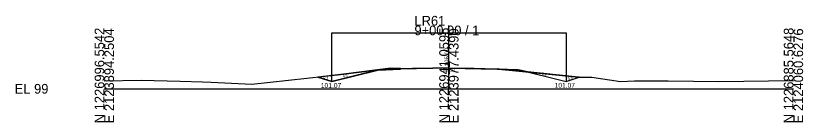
# Model space of a CAD drawing. Extents: x 2121193 to 2127979, y 1225108 to 1234639.
# Drawn here: x 2126750.9 to 2126979.4, y 1234107.5 to 1234138.4 of the extents above; entities that cross this region are included whole.
import ezdxf

# ---------------------------------------------------------------- set-up
doc = ezdxf.new("R2010")
doc.units = 0
for name, color, linetype in [('XS_CELL', 7, 'Continuous'), ('XS_M_DITCH', 7, 'Continuous'), ('XS_M_SHAPES_EARTHWORK', 7, 'Continuous'), ('XS_P_FINISHED_GRADE', 7, 'Continuous'), ('XS_P_FINISHED_GRADE_ELEV_TX', 7, 'Continuous'), ('XS_P_SUBGRADE_GRANULAR', 7, 'Continuous'), ('XS_P_SUBGRADE_PAVEMENT', 7, 'Continuous'), ('XS_P_TX_DCH', 7, 'Continuous'), ('XS_P_TX_FS_BS', 7, 'Continuous'), ('XS_X_GROUND', 7, 'Continuous'), ('XS_X_GROUND_TX', 7, 'Continuous')]:
    doc.layers.add(name, color=color, linetype=linetype)

msp = doc.modelspace()

# ---------------------------------------------------------------- linework, layer by layer
at = {"layer": 'XS_CELL'}
for p, q in [((2126876.61, 1234117.21), (2126876.61, 1234135.52)), ((2126776.61, 1234117.21), (2126876.61, 1234117.21)), ((2126876.61, 1234117.21), (2126976.61, 1234117.21))]:
    msp.add_line(p, q, dxfattribs=at)
at = {"layer": 'XS_M_DITCH'}
for p, q in [((2126842.61, 1234119.28), (2126842.61, 1234133.39)), ((2126842.61, 1234133.39), (2126910.61, 1234133.39)), ((2126910.61, 1234133.39), (2126910.61, 1234119.28))]:
    msp.add_line(p, q, dxfattribs=at)
at = {"layer": 'XS_M_SHAPES_EARTHWORK'}
for p, q in [((2126859.71, 1234123.21), (2126846.06, 1234121.41)), ((2126856.02, 1234122.63), (2126862.54, 1234122.89)), ((2126856.61, 1234122.78), (2126856.02, 1234122.63)), ((2126856.61, 1234122.78), (2126862.61, 1234123.02)), ((2126862.61, 1234123.02), (2126856.61, 1234122.78)), ((2126861.73, 1234123.11), (2126859.71, 1234123.21)), ((2126862.61, 1234123.12), (2126861.73, 1234123.11)), ((2126862.54, 1234122.89), (2126862.61, 1234123.02)), ((2126862.61, 1234123.02), (2126862.61, 1234123.12)), ((2126891.99, 1234122.84), (2126890.63, 1234122.98)), ((2126890.63, 1234122.98), (2126890.68, 1234122.89)), ((2126890.68, 1234122.89), (2126891.99, 1234122.84)), ((2126897.2, 1234122.63), (2126891.99, 1234122.84)), ((2126891.99, 1234122.84), (2126899.44, 1234122.07)), ((2126899.44, 1234122.07), (2126897.2, 1234122.63)), ((2126914.27, 1234120.54), (2126899.44, 1234122.07)), ((2126899.44, 1234122.07), (2126910.61, 1234119.28)), ((2126846.06, 1234121.41), (2126838.62, 1234120.61)), ((2126838.62, 1234120.61), (2126842.61, 1234119.28)), ((2126910.61, 1234119.28), (2126914.39, 1234120.54)), ((2126914.39, 1234120.54), (2126914.27, 1234120.54))]:
    msp.add_line(p, q, dxfattribs=at)
msp.add_lwpolyline([(2126842.61, 1234119.28), (2126856.02, 1234122.63), (2126856.61, 1234122.78)], dxfattribs=at)
at = {"layer": 'XS_P_FINISHED_GRADE'}
for p, q in [((2126856.61, 1234122.78), (2126842.61, 1234119.28)), ((2126862.61, 1234123.02), (2126856.61, 1234122.78)), ((2126876.61, 1234123.3), (2126862.61, 1234123.02)), ((2126876.61, 1234123.3), (2126890.61, 1234123.02)), ((2126890.61, 1234123.02), (2126896.61, 1234122.78)), ((2126896.61, 1234122.78), (2126910.61, 1234119.28)), ((2126842.61, 1234119.28), (2126838.62, 1234120.61)), ((2126910.61, 1234119.28), (2126914.39, 1234120.54))]:
    msp.add_line(p, q, dxfattribs=at)
at = {"layer": 'XS_P_SUBGRADE_GRANULAR'}
for p, q in [((2126862.54, 1234122.89), (2126856.02, 1234122.63)), ((2126890.68, 1234122.89), (2126897.2, 1234122.63))]:
    msp.add_line(p, q, dxfattribs=at)
at = {"layer": 'XS_P_SUBGRADE_PAVEMENT'}
for p, q in [((2126876.61, 1234123.17), (2126862.54, 1234122.89)), ((2126862.61, 1234123.02), (2126862.54, 1234122.89)), ((2126876.61, 1234123.17), (2126890.68, 1234122.89)), ((2126890.61, 1234123.02), (2126890.68, 1234122.89))]:
    msp.add_line(p, q, dxfattribs=at)
at = {"layer": 'XS_X_GROUND'}
for p, q in [((2126846.06, 1234121.41), (2126859.71, 1234123.21)), ((2126859.71, 1234123.21), (2126861.73, 1234123.11)), ((2126861.73, 1234123.11), (2126866.03, 1234123.17)), ((2126866.03, 1234123.17), (2126876.05, 1234123.31)), ((2126876.05, 1234123.31), (2126876.61, 1234123.3)), ((2126876.61, 1234123.3), (2126883.92, 1234123.15)), ((2126883.92, 1234123.15), (2126890.34, 1234123.01)), ((2126890.34, 1234123.01), (2126914.27, 1234120.54)), ((2126776.61, 1234119.54), (2126787.36, 1234119.66)), ((2126787.36, 1234119.66), (2126798.62, 1234119.46)), ((2126819.38, 1234118.55), (2126846.06, 1234121.41)), ((2126914.27, 1234120.54), (2126918.1, 1234120.53)), ((2126918.1, 1234120.53), (2126926.43, 1234119.27)), ((2126926.43, 1234119.27), (2126930.49, 1234119.48)), ((2126930.49, 1234119.48), (2126940.23, 1234119.49)), ((2126940.23, 1234119.49), (2126954.96, 1234119.32)), ((2126954.96, 1234119.32), (2126976.61, 1234119.61)), ((2126798.62, 1234119.46), (2126805.12, 1234119.19)), ((2126805.12, 1234119.19), (2126807.64, 1234119.13)), ((2126807.64, 1234119.13), (2126819.38, 1234118.55))]:
    msp.add_line(p, q, dxfattribs=at)

# ---------------------------------------------------------------- texts
at = {"layer": 'XS_CELL'}
for s, p in [('LR61', (2126866.61, 1234135.52)), ('9+00.00 / 1', (2126866.61, 1234132.72)), ('EL 99', (2126750.61, 1234115.81))]:
    msp.add_text(s, height=2.8, dxfattribs=at).set_placement(p)
for s, p in [('N 1226996.5542', (2126776.61, 1234107.21)), ('E 2123894.2504', (2126779.41, 1234107.21)), ('N 1226941.0595', (2126876.61, 1234107.21)), ('E 2123977.4390', (2126879.41, 1234107.21)), ('N 1226885.5648', (2126976.61, 1234107.21)), ('E 2124060.6276', (2126979.41, 1234107.21))]:
    msp.add_text(s, height=2.8, rotation=90, dxfattribs=at).set_placement(p)
at = {"layer": 'XS_P_FINISHED_GRADE_ELEV_TX'}
msp.add_text(' 105.09', height=1.25, rotation=90, dxfattribs=at).set_placement((2126876.61, 1234123.3))
at = {"layer": 'XS_P_TX_DCH'}
for p in [(2126839.45, 1234117.46), (2126907.29, 1234117.52)]:
    msp.add_text('101.07', height=1.4, dxfattribs=at).set_placement(p)
at = {"layer": 'XS_P_TX_FS_BS'}
for s, rotation, p in [('4:1', 345.9638, (2126903.38, 1234121.34)), ('3:1', 341.5651, (2126840.11, 1234120.31)), ('4:1', 14.0362, (2126845.89, 1234120.46)), ('3:1', 18.4349, (2126911.21, 1234119.62))]:
    msp.add_text(s, height=0.8, rotation=rotation, dxfattribs=at).set_placement(p)
at = {"layer": 'XS_X_GROUND_TX'}
msp.add_text('105.09', height=1, dxfattribs=at).set_placement((2126874.05, 1234122.14))

doc.saveas('drawing.dxf')
